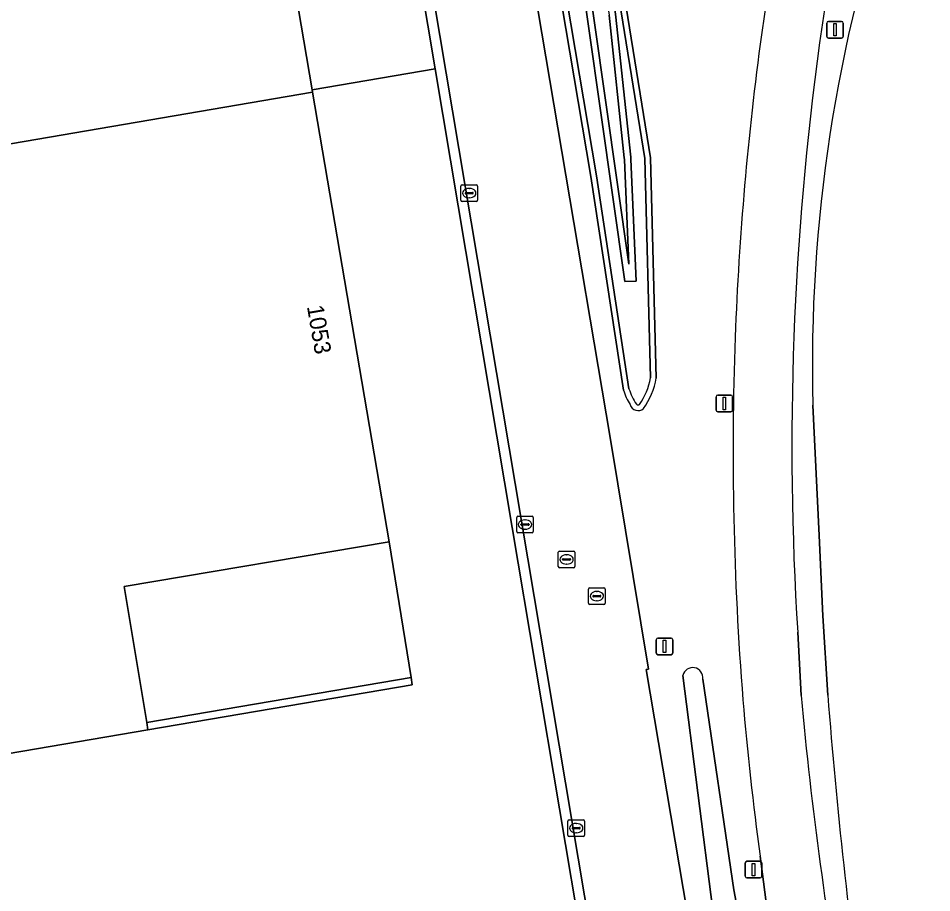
# Model space of a CAD drawing. Extents: x 154324 to 155744, y 382937 to 384188.
# Drawn here: x 154972.4 to 155027.3, y 383769.7 to 383822.2 of the extents above; entities that cross this region are included whole.
import ezdxf

# ---------------------------------------------------------------- set-up
doc = ezdxf.new("R2010")
doc.units = 0
for name, color, linetype in [('IMGEO_Berm_groen', 7, 'Continuous'), ('IMGEO_Erf', 7, 'Continuous'), ('IMGEO_Fietspad_gesloten', 7, 'Continuous'), ('IMGEO_Gemengd_bos', 7, 'Continuous'), ('IMGEO_Groenvoorziening', 7, 'Continuous'), ('IMGEO_Kolk', 7, 'Continuous'), ('IMGEO_Lichtmast', 7, 'Continuous'), ('IMGEO_Muur', 7, 'Continuous'), ('IMGEO_Oever', 7, 'Continuous'), ('IMGEO_Pand', 7, 'Continuous'), ('IMGEO_Pand_nummerreeks', 7, 'Continuous'), ('IMGEO_Pand_overbouw', 7, 'Continuous'), ('IMGEO_Rijbaan_lokaal_gesloten', 7, 'Continuous'), ('IMGEO_Rijbaan_lokaal_open', 7, 'Continuous'), ('IMGEO_Rijbaan_regionaal_gesloten', 7, 'Continuous'), ('IMGEO_Rioolput', 7, 'Continuous'), ('IMGEO_Voetpad_open', 7, 'Continuous'), ('IMGEO_Waterloop', 7, 'Continuous')]:
    doc.layers.add(name, color=color, linetype=linetype)

msp = doc.modelspace()

# ---------------------------------------------------------------- linework, layer by layer
at = {"layer": 'IMGEO_Berm_groen'}
for points in [[(155021.062, 383781.526), (155020.777, 383786.304), (155020.543, 383791.131), (155020.164, 383798.965)], [(155019.258, 383785.319), (155019.458, 383781.506)]]:
    msp.add_lwpolyline(points, dxfattribs=at)
for centre, radius, start, end in [((155210.029, 383793.629), 191.389, 160.20529, 171.8567), ((155112.774, 383801.258), 92.638, 161.2191, 181.41836), ((155196.336, 383796.494), 177.431, 172.14628, 183.61105), ((155254.724, 383803.119), 236.257, 185.24892, 190.19973), ((155354.041, 383807.716), 334.007, 184.49728, 188.0146)]:
    msp.add_arc(centre, radius, start, end, dxfattribs=at)
at = {"layer": 'IMGEO_Erf'}
msp.add_lwpolyline([(155006.354, 383766.232), (155002.093, 383791.612), (154997.464, 383819.179), (154990.053, 383817.92), (154990.078, 383817.772), (154994.697, 383790.754), (154996.007, 383782.588), (154996.077, 383782.155), (154980.188, 383779.449), (154932.104, 383771.258), (154925.989, 383806.82), (154925.972, 383806.919), (154922.478, 383806.318), (154926.099, 383785.26), (154925.991, 383785.242), (154933.724, 383739.787)], dxfattribs=at)
msp.add_lwpolyline([(154994.697, 383790.754), (154978.752, 383788.053), (154980.116, 383779.881), (154996.007, 383782.588)], close=True, dxfattribs=at)
at = {"layer": 'IMGEO_Fietspad_gesloten'}
for points in [[(155019.458, 383781.506), (155019.258, 383785.319)], [(155016.997, 383771.855), (155017.48, 383768.134), (155017.908, 383765.009), (155017.961, 383764.734)]]:
    msp.add_lwpolyline(points, dxfattribs=at)
for centre, radius, start, end in [((155205.608, 383794.513), 190.42, 159.9547, 171.93294), ((155210.029, 383793.629), 191.389, 160.20529, 171.8567), ((155201.034, 383796.14), 185.665, 172.23195, 177.86583), ((155196.336, 383796.494), 177.431, 172.14628, 183.61105), ((155203.954, 383796.145), 188.584, 177.90058, 184.53181), ((155202.195, 383797.06), 186.905, 184.85386, 187.75017), ((155254.724, 383803.119), 236.257, 185.24892, 190.19973)]:
    msp.add_arc(centre, radius, start, end, dxfattribs=at)
at = {"layer": 'IMGEO_Gemengd_bos'}
msp.add_lwpolyline([(154997.582, 383876.452), (155005.612, 383831.964), (155009.111, 383807.437), (155008.833, 383813.728), (155008.825, 383813.835), (155007.915, 383822.409)], dxfattribs=at)
at = {"layer": 'IMGEO_Groenvoorziening'}
for points in [[(155004.825, 383886.546), (155002.919, 383883.925), (155001.914, 383882.537), (154999.781, 383879.589), (155010.405, 383813.833), (155010.749, 383800.586)], [(155008.779, 383799.869), (155006.822, 383812.702), (154997.022, 383870.738), (154996.525, 383874.017)], [(154996.312, 383868.192), (154996.943, 383862.793), (155002.174, 383831.432), (155007.976, 383797.016), (155010.285, 383783.102), (155010.136, 383783.072), (155013.373, 383763.974), (155014.065, 383763.349), (155014.521, 383763.048)], [(155015.423, 383769.821), (155016.43, 383764.411), (155015.09, 383764.123), (155014.16, 383768.6), (155012.356, 383782.715)], [(155013.549, 383782.498), (155015.423, 383769.821)], [(155017.961, 383764.734), (155017.908, 383765.009), (155017.48, 383768.134), (155016.997, 383771.855)]]:
    msp.add_lwpolyline(points, dxfattribs=at)
for centre, radius, start, end in [((155205.608, 383794.513), 190.42, 159.9547, 171.93294), ((155201.034, 383796.14), 185.665, 172.23195, 177.86583), ((155203.954, 383796.145), 188.584, 177.90058, 184.53181), ((155006.277, 383801.378), 4.542, 324.7543, 349.957), ((155012.447, 383801.006), 3.84, 197.2177, 211.5913), ((155009.659, 383799.143), 0.506, 197.1336, 310.2482), ((155012.948, 383782.58), 0.607, 352.2319, 167.15), ((155202.195, 383797.06), 186.905, 184.85386, 187.75017)]:
    msp.add_arc(centre, radius, start, end, dxfattribs=at)
at = {"layer": 'IMGEO_Kolk'}
for p, q in [((154999.005, 383811.285), (154999.005, 383812.137)), ((154999.08, 383812.211), (154999.932, 383812.211)), ((154999.493, 383811.991), (154999.518, 383811.991)), ((155000.006, 383812.137), (155000.006, 383811.285)), ((154999.264, 383811.705), (154999.264, 383811.717)), ((154999.702, 383811.668), (154999.304, 383811.668)), ((154999.307, 383811.754), (154999.705, 383811.754)), ((154999.516, 383811.431), (154999.491, 383811.431)), ((154999.748, 383811.717), (154999.748, 383811.705)), ((154999.932, 383811.211), (154999.08, 383811.211)), ((155002.357, 383791.359), (155002.357, 383792.211)), ((155002.432, 383792.285), (155003.284, 383792.285)), ((155003.358, 383792.211), (155003.358, 383791.359)), ((155002.616, 383791.779), (155002.616, 383791.791)), ((155003.054, 383791.742), (155002.656, 383791.742)), ((155002.659, 383791.828), (155003.057, 383791.828)), ((155002.845, 383792.065), (155002.87, 383792.065)), ((155003.1, 383791.791), (155003.1, 383791.779)), ((155003.284, 383791.285), (155002.432, 383791.285)), ((155002.868, 383791.505), (155002.843, 383791.505)), ((155005.512, 383774.035), (155006.364, 383774.035)), ((155005.437, 383773.109), (155005.437, 383773.961)), ((155005.696, 383773.529), (155005.696, 383773.541)), ((155006.134, 383773.492), (155005.736, 383773.492)), ((155005.739, 383773.578), (155006.137, 383773.578)), ((155005.925, 383773.815), (155005.95, 383773.815)), ((155006.18, 383773.541), (155006.18, 383773.529)), ((155006.438, 383773.961), (155006.438, 383773.109)), ((155006.364, 383773.035), (155005.512, 383773.035)), ((155005.948, 383773.255), (155005.923, 383773.255))]:
    msp.add_line(p, q, dxfattribs=at)
for points in [[(154999.005, 383811.285), (154999.005, 383812.137)], [(154999.08, 383812.211), (154999.932, 383812.211)], [(155000.006, 383812.137), (155000.006, 383811.285)], [(154999.932, 383811.211), (154999.08, 383811.211)], [(155002.357, 383791.359), (155002.357, 383792.211)], [(155002.432, 383792.285), (155003.284, 383792.285)], [(155003.358, 383792.211), (155003.358, 383791.359)], [(155003.284, 383791.285), (155002.432, 383791.285)], [(155005.512, 383774.035), (155006.364, 383774.035)], [(155005.437, 383773.109), (155005.437, 383773.961)], [(155006.438, 383773.961), (155006.438, 383773.109)], [(155006.364, 383773.035), (155005.512, 383773.035)]]:
    msp.add_lwpolyline(points, dxfattribs=at)
for centre, radius, start, end in [((154999.082, 383812.135), 0.0765, 91.552, 178.448), ((154999.082, 383812.135), 0.0765, 91.552, 178.448), ((154999.93, 383812.135), 0.0765, 1.552, 88.448), ((154999.93, 383812.135), 0.0765, 1.552, 88.448), ((154999.304, 383811.714), 0.0403, 85.8775, 175.7526), ((154999.301, 383811.704), 0.0366, 178.938, 274.7102), ((154999.705, 383811.711), 0.043, 264.8664, 352.4533), ((154999.709, 383811.716), 0.0386, 1.7309, 96.639), ((154999.082, 383811.287), 0.0765, 181.552, 268.448), ((154999.082, 383811.287), 0.0765, 181.552, 268.448), ((154999.93, 383811.287), 0.0765, 271.552, 358.448), ((154999.93, 383811.287), 0.0765, 271.552, 358.448), ((155002.434, 383792.209), 0.0765, 91.552, 178.448), ((155002.434, 383792.209), 0.0765, 91.552, 178.448), ((155003.282, 383792.209), 0.0765, 1.552, 88.448), ((155003.282, 383792.209), 0.0765, 1.552, 88.448), ((155002.656, 383791.788), 0.0403, 85.8775, 175.7526), ((155002.653, 383791.778), 0.0366, 178.938, 274.7102), ((155003.057, 383791.785), 0.043, 264.8664, 352.4533), ((155003.061, 383791.79), 0.0386, 1.7309, 96.639), ((155002.434, 383791.361), 0.0765, 181.552, 268.448), ((155002.434, 383791.361), 0.0765, 181.552, 268.448), ((155003.282, 383791.361), 0.0765, 271.552, 358.448), ((155003.282, 383791.361), 0.0765, 271.552, 358.448), ((155005.514, 383773.959), 0.0765, 91.552, 178.448), ((155005.514, 383773.959), 0.0765, 91.552, 178.448), ((155006.362, 383773.959), 0.0765, 1.552, 88.448), ((155006.362, 383773.959), 0.0765, 1.552, 88.448), ((155005.736, 383773.538), 0.0403, 85.8775, 175.7526), ((155005.733, 383773.528), 0.0366, 178.938, 274.7102), ((155006.137, 383773.535), 0.043, 264.8664, 352.4533), ((155006.141, 383773.54), 0.0386, 1.7309, 96.639), ((155005.514, 383773.111), 0.0765, 181.552, 268.448), ((155005.514, 383773.111), 0.0765, 181.552, 268.448), ((155006.362, 383773.111), 0.0765, 271.552, 358.448), ((155006.362, 383773.111), 0.0765, 271.552, 358.448)]:
    msp.add_arc(centre, radius, start, end, dxfattribs=at)
for centre, major_axis, ratio, start_param, end_param in [((154999.492, 383811.711), (-0.387, 0.002), 0.722429, 4.712389, 7.853982), ((154999.517, 383811.711), (-0.39, 0.002), 0.717154, 1.570796, 4.712389), ((155002.844, 383791.785), (-0.387, 0.002), 0.722429, 4.712389, 7.853982), ((155002.869, 383791.785), (-0.39, 0.002), 0.717154, 1.570796, 4.712389), ((155005.924, 383773.535), (-0.387, 0.002), 0.722429, 4.712389, 7.853982), ((155005.949, 383773.535), (-0.39, 0.002), 0.717154, 1.570796, 4.712389)]:
    msp.add_ellipse(centre, major_axis=major_axis, ratio=ratio, start_param=start_param, end_param=end_param, dxfattribs=at)
at = {"layer": 'IMGEO_Lichtmast'}
for p, q in [((155021.008, 383821.134), (155021.008, 383821.934)), ((155021.008, 383821.934), (155021.008, 383821.134)), ((155021.108, 383822.034), (155021.898, 383822.034)), ((155021.898, 383822.034), (155021.108, 383822.034)), ((155021.998, 383821.934), (155021.998, 383821.134)), ((155021.998, 383821.134), (155021.998, 383821.934)), ((155021.898, 383821.034), (155021.108, 383821.034)), ((155021.108, 383821.034), (155021.898, 383821.034)), ((155014.349, 383798.665), (155014.349, 383799.465)), ((155014.349, 383799.465), (155014.349, 383798.665)), ((155014.449, 383799.565), (155015.239, 383799.565)), ((155015.239, 383799.565), (155014.449, 383799.565)), ((155015.339, 383799.465), (155015.339, 383798.665)), ((155015.339, 383798.665), (155015.339, 383799.465)), ((155015.239, 383798.565), (155014.449, 383798.565)), ((155014.449, 383798.565), (155015.239, 383798.565)), ((155010.749, 383784.063), (155010.749, 383784.863)), ((155010.749, 383784.863), (155010.749, 383784.063)), ((155010.849, 383784.963), (155011.639, 383784.963)), ((155011.639, 383784.963), (155010.849, 383784.963)), ((155011.739, 383784.863), (155011.739, 383784.063)), ((155011.739, 383784.063), (155011.739, 383784.863)), ((155011.639, 383783.963), (155010.849, 383783.963)), ((155010.849, 383783.963), (155011.639, 383783.963)), ((155016.101, 383770.641), (155016.101, 383771.441)), ((155016.101, 383771.441), (155016.101, 383770.641)), ((155016.201, 383771.541), (155016.991, 383771.541)), ((155016.991, 383771.541), (155016.201, 383771.541)), ((155017.091, 383771.441), (155017.091, 383770.641)), ((155017.091, 383770.641), (155017.091, 383771.441)), ((155016.991, 383770.541), (155016.201, 383770.541)), ((155016.201, 383770.541), (155016.991, 383770.541))]:
    msp.add_line(p, q, dxfattribs=at)
for points in [[(155021.428, 383821.909), (155021.578, 383821.909), (155021.578, 383821.159), (155021.428, 383821.159), (155021.428, 383821.909)], [(155014.769, 383799.44), (155014.919, 383799.44), (155014.919, 383798.69), (155014.769, 383798.69), (155014.769, 383799.44)], [(155011.169, 383784.838), (155011.319, 383784.838), (155011.319, 383784.088), (155011.169, 383784.088), (155011.169, 383784.838)], [(155016.521, 383771.416), (155016.671, 383771.416), (155016.671, 383770.666), (155016.521, 383770.666), (155016.521, 383771.416)]]:
    msp.add_lwpolyline(points, dxfattribs=at)
for centre, start, end in [((155021.108, 383821.934), 90, 180), ((155021.108, 383821.934), 90, 180), ((155021.898, 383821.934), 0, 90), ((155021.898, 383821.934), 360, 90), ((155021.108, 383821.134), 180, 270), ((155021.108, 383821.134), 180, 270), ((155021.898, 383821.134), 270, 0), ((155021.898, 383821.134), 270, 0), ((155014.449, 383799.465), 90, 180), ((155014.449, 383799.465), 90, 180), ((155015.239, 383799.465), 0, 90), ((155015.239, 383799.465), 360, 90), ((155014.449, 383798.665), 180, 270), ((155014.449, 383798.665), 180, 270), ((155015.239, 383798.665), 270, 0), ((155015.239, 383798.665), 270, 0), ((155010.849, 383784.863), 90, 180), ((155010.849, 383784.863), 90, 180), ((155011.639, 383784.863), 0, 90), ((155011.639, 383784.863), 360, 90), ((155010.849, 383784.063), 180, 270), ((155010.849, 383784.063), 180, 270), ((155011.639, 383784.063), 270, 0), ((155011.639, 383784.063), 270, 0), ((155016.201, 383771.441), 90, 180), ((155016.201, 383771.441), 90, 180), ((155016.991, 383771.441), 0, 90), ((155016.991, 383771.441), 360, 90), ((155016.201, 383770.641), 180, 270), ((155016.201, 383770.641), 180, 270), ((155016.991, 383770.641), 270, 0), ((155016.991, 383770.641), 270, 0)]:
    msp.add_arc(centre, 0.1, start, end, dxfattribs=at)
at = {"layer": 'IMGEO_Muur'}
msp.add_lwpolyline([(154996.077, 383782.155), (154996.007, 383782.588), (154980.116, 383779.881), (154980.188, 383779.449)], close=True, dxfattribs=at)
at = {"layer": 'IMGEO_Oever'}
for points in [[(155010.749, 383800.586), (155010.405, 383813.833), (154999.781, 383879.589), (154999.501, 383879.202), (155000.837, 383870.939), (155010.067, 383813.801), (155010.409, 383800.612)], [(154997.285, 383875.907), (155005.228, 383831.902), (155008.867, 383806.395), (155009.545, 383806.425), (155009.221, 383813.751), (155009.212, 383813.87), (155008.3, 383822.46), (155000.394, 383872.059), (154999.197, 383878.781), (154998.88, 383878.344), (155000.011, 383871.994), (155007.915, 383822.409), (155008.825, 383813.835), (155008.833, 383813.728), (155009.111, 383807.437), (155005.612, 383831.964), (154997.582, 383876.452)], [(155009.11, 383799.946), (155007.157, 383812.756), (154997.357, 383870.792), (154996.761, 383874.717)], [(154996.525, 383874.017), (154997.022, 383870.738), (155006.822, 383812.702), (155008.779, 383799.869)]]:
    msp.add_lwpolyline(points, dxfattribs=at)
for centre, radius, start, end in [((155006.381, 383801.334), 4.092, 325.1656, 349.8317), ((155006.277, 383801.378), 4.542, 324.7543, 349.957), ((155012.447, 383801.006), 3.84, 197.2177, 211.5913), ((155013.167, 383801.306), 4.279, 198.5266, 212.3666), ((155009.659, 383799.143), 0.506, 197.1336, 310.2482), ((155009.66, 383799.142), 0.166, 229.9446, 299.059)]:
    msp.add_arc(centre, radius, start, end, dxfattribs=at)
at = {"layer": 'IMGEO_Pand'}
msp.add_lwpolyline([(154962.788, 383873.403), (154930.221, 383858.416), (154936.2, 383845.476), (154938.531, 383840.433), (154922.044, 383832.788), (154921.562, 383832.565), (154925.972, 383806.919), (154925.989, 383806.82), (154990.078, 383817.772), (154990.053, 383817.92), (154983.065, 383859.056)], dxfattribs=at)
msp.add_lwpolyline([(154994.697, 383790.754), (154990.078, 383817.772), (154925.989, 383806.82), (154932.104, 383771.258), (154980.188, 383779.449), (154980.116, 383779.881), (154978.752, 383788.053)], close=True, dxfattribs=at)
at = {"layer": 'IMGEO_Pand_overbouw'}
msp.add_lwpolyline([(154994.697, 383790.754), (154978.752, 383788.053), (154980.188, 383779.449), (154996.077, 383782.155), (154996.007, 383782.588)], close=True, dxfattribs=at)
at = {"layer": 'IMGEO_Rijbaan_lokaal_gesloten'}
msp.add_lwpolyline([(154990.18, 383866.132), (155008.692, 383756.004), (155014.572, 383756.911), (155014.481, 383757.434), (155013.373, 383763.974), (155010.136, 383783.072), (155010.285, 383783.102), (155007.976, 383797.016), (155002.174, 383831.432), (154996.943, 383862.793), (154995.411, 383871.976)], dxfattribs=at)
at = {"layer": 'IMGEO_Rijbaan_lokaal_open'}
msp.add_lwpolyline([(154989.689, 383865.488), (154997.464, 383819.179), (155002.093, 383791.612), (155006.354, 383766.232), (155008.641, 383752.609), (155011.19, 383737.428), (155012.365, 383730.431), (155013.835, 383721.664), (155016.277, 383707.107), (155016.871, 383707.197), (155013.247, 383728.802), (155012.973, 383730.527), (155008.692, 383756.004), (154990.18, 383866.132)], dxfattribs=at)
at = {"layer": 'IMGEO_Rijbaan_regionaal_gesloten'}
msp.add_lwpolyline([(155020.164, 383798.965), (155020.543, 383791.131), (155020.777, 383786.304), (155021.062, 383781.526)], dxfattribs=at)
for centre, radius, start, end in [((155112.774, 383801.258), 92.638, 161.2191, 181.41836), ((155354.041, 383807.716), 334.007, 184.49728, 188.0146)]:
    msp.add_arc(centre, radius, start, end, dxfattribs=at)
at = {"layer": 'IMGEO_Rioolput'}
for p, q in [((155004.86, 383789.265), (155004.86, 383790.117)), ((155004.935, 383790.191), (155005.787, 383790.191)), ((155005.348, 383789.971), (155005.373, 383789.971)), ((155005.861, 383790.117), (155005.861, 383789.265)), ((155005.119, 383789.685), (155005.119, 383789.697)), ((155005.557, 383789.648), (155005.159, 383789.648)), ((155005.162, 383789.734), (155005.56, 383789.734)), ((155005.603, 383789.697), (155005.603, 383789.685)), ((155005.787, 383789.191), (155004.935, 383789.191)), ((155005.371, 383789.411), (155005.346, 383789.411)), ((155006.679, 383787.057), (155006.679, 383787.909)), ((155006.754, 383787.983), (155007.606, 383787.983)), ((155007.68, 383787.909), (155007.68, 383787.057)), ((155006.938, 383787.477), (155006.938, 383787.489)), ((155007.376, 383787.44), (155006.978, 383787.44)), ((155006.981, 383787.526), (155007.379, 383787.526)), ((155007.167, 383787.763), (155007.192, 383787.763)), ((155007.422, 383787.489), (155007.422, 383787.477)), ((155007.606, 383786.983), (155006.754, 383786.983)), ((155007.19, 383787.203), (155007.165, 383787.203))]:
    msp.add_line(p, q, dxfattribs=at)
for points in [[(155004.86, 383789.265), (155004.86, 383790.117)], [(155004.935, 383790.191), (155005.787, 383790.191)], [(155005.861, 383790.117), (155005.861, 383789.265)], [(155005.787, 383789.191), (155004.935, 383789.191)], [(155006.679, 383787.057), (155006.679, 383787.909)], [(155006.754, 383787.983), (155007.606, 383787.983)], [(155007.68, 383787.909), (155007.68, 383787.057)], [(155007.606, 383786.983), (155006.754, 383786.983)]]:
    msp.add_lwpolyline(points, dxfattribs=at)
for centre, radius, start, end in [((155004.937, 383790.115), 0.0765, 91.552, 178.448), ((155004.937, 383790.115), 0.0765, 91.552, 178.448), ((155005.785, 383790.115), 0.0765, 1.552, 88.448), ((155005.785, 383790.115), 0.0765, 1.552, 88.448), ((155005.159, 383789.694), 0.0403, 85.8775, 175.7526), ((155005.156, 383789.684), 0.0366, 178.938, 274.7102), ((155005.56, 383789.691), 0.043, 264.8664, 352.4533), ((155005.564, 383789.696), 0.0386, 1.7309, 96.639), ((155004.937, 383789.267), 0.0765, 181.552, 268.448), ((155004.937, 383789.267), 0.0765, 181.552, 268.448), ((155005.785, 383789.267), 0.0765, 271.552, 358.448), ((155005.785, 383789.267), 0.0765, 271.552, 358.448), ((155006.756, 383787.907), 0.0765, 91.552, 178.448), ((155006.756, 383787.907), 0.0765, 91.552, 178.448), ((155007.604, 383787.907), 0.0765, 1.552, 88.448), ((155007.604, 383787.907), 0.0765, 1.552, 88.448), ((155006.978, 383787.486), 0.0403, 85.8775, 175.7526), ((155006.975, 383787.476), 0.0366, 178.938, 274.7102), ((155007.379, 383787.483), 0.043, 264.8664, 352.4533), ((155007.383, 383787.488), 0.0386, 1.7309, 96.639), ((155006.756, 383787.059), 0.0765, 181.552, 268.448), ((155006.756, 383787.059), 0.0765, 181.552, 268.448), ((155007.604, 383787.059), 0.0765, 271.552, 358.448), ((155007.604, 383787.059), 0.0765, 271.552, 358.448)]:
    msp.add_arc(centre, radius, start, end, dxfattribs=at)
for centre, major_axis, ratio, start_param, end_param in [((155005.347, 383789.691), (-0.387, 0.002), 0.722429, 4.712389, 7.853982), ((155005.372, 383789.691), (-0.39, 0.002), 0.717154, 1.570796, 4.712389), ((155007.166, 383787.483), (-0.387, 0.002), 0.722429, 4.712389, 7.853982), ((155007.191, 383787.483), (-0.39, 0.002), 0.717154, 1.570796, 4.712389)]:
    msp.add_ellipse(centre, major_axis=major_axis, ratio=ratio, start_param=start_param, end_param=end_param, dxfattribs=at)
at = {"layer": 'IMGEO_Voetpad_open'}
msp.add_lwpolyline([(154982.447, 383862.688), (154982.803, 383862.747), (154982.843, 383862.511), (154981.758, 383862.33), (154982.276, 383859.173), (154983.382, 383859.351), (154983.42, 383859.114), (154983.065, 383859.056), (154990.053, 383817.92), (154997.464, 383819.179), (154989.689, 383865.488)], dxfattribs=at)
at = {"layer": 'IMGEO_Waterloop'}
for points in [[(155010.409, 383800.612), (155010.067, 383813.801), (155000.837, 383870.939), (154999.501, 383879.202), (154999.197, 383878.781), (155000.394, 383872.059), (155008.3, 383822.46), (155009.212, 383813.87), (155009.221, 383813.751), (155009.545, 383806.425), (155008.867, 383806.395), (155005.228, 383831.902), (154997.285, 383875.907)], [(154996.761, 383874.717), (154997.357, 383870.792), (155007.157, 383812.756), (155009.11, 383799.946)], [(155012.356, 383782.715), (155014.16, 383768.6)], [(155014.16, 383768.6), (155015.09, 383764.123), (155016.43, 383764.411), (155015.423, 383769.821), (155013.549, 383782.498)]]:
    msp.add_lwpolyline(points, dxfattribs=at)
for centre, radius, start, end in [((155006.381, 383801.334), 4.092, 325.1656, 349.8317), ((155013.167, 383801.306), 4.279, 198.5266, 212.3666), ((155009.66, 383799.142), 0.166, 229.9446, 299.059), ((155012.948, 383782.58), 0.607, 352.2319, 167.15)]:
    msp.add_arc(centre, radius, start, end, dxfattribs=at)

# ---------------------------------------------------------------- texts
at = {"layer": 'IMGEO_Pand_nummerreeks'}
msp.add_text('1053', height=1, rotation=279.7, dxfattribs=at).set_placement((154989.742, 383804.899))

doc.saveas('drawing.dxf')
